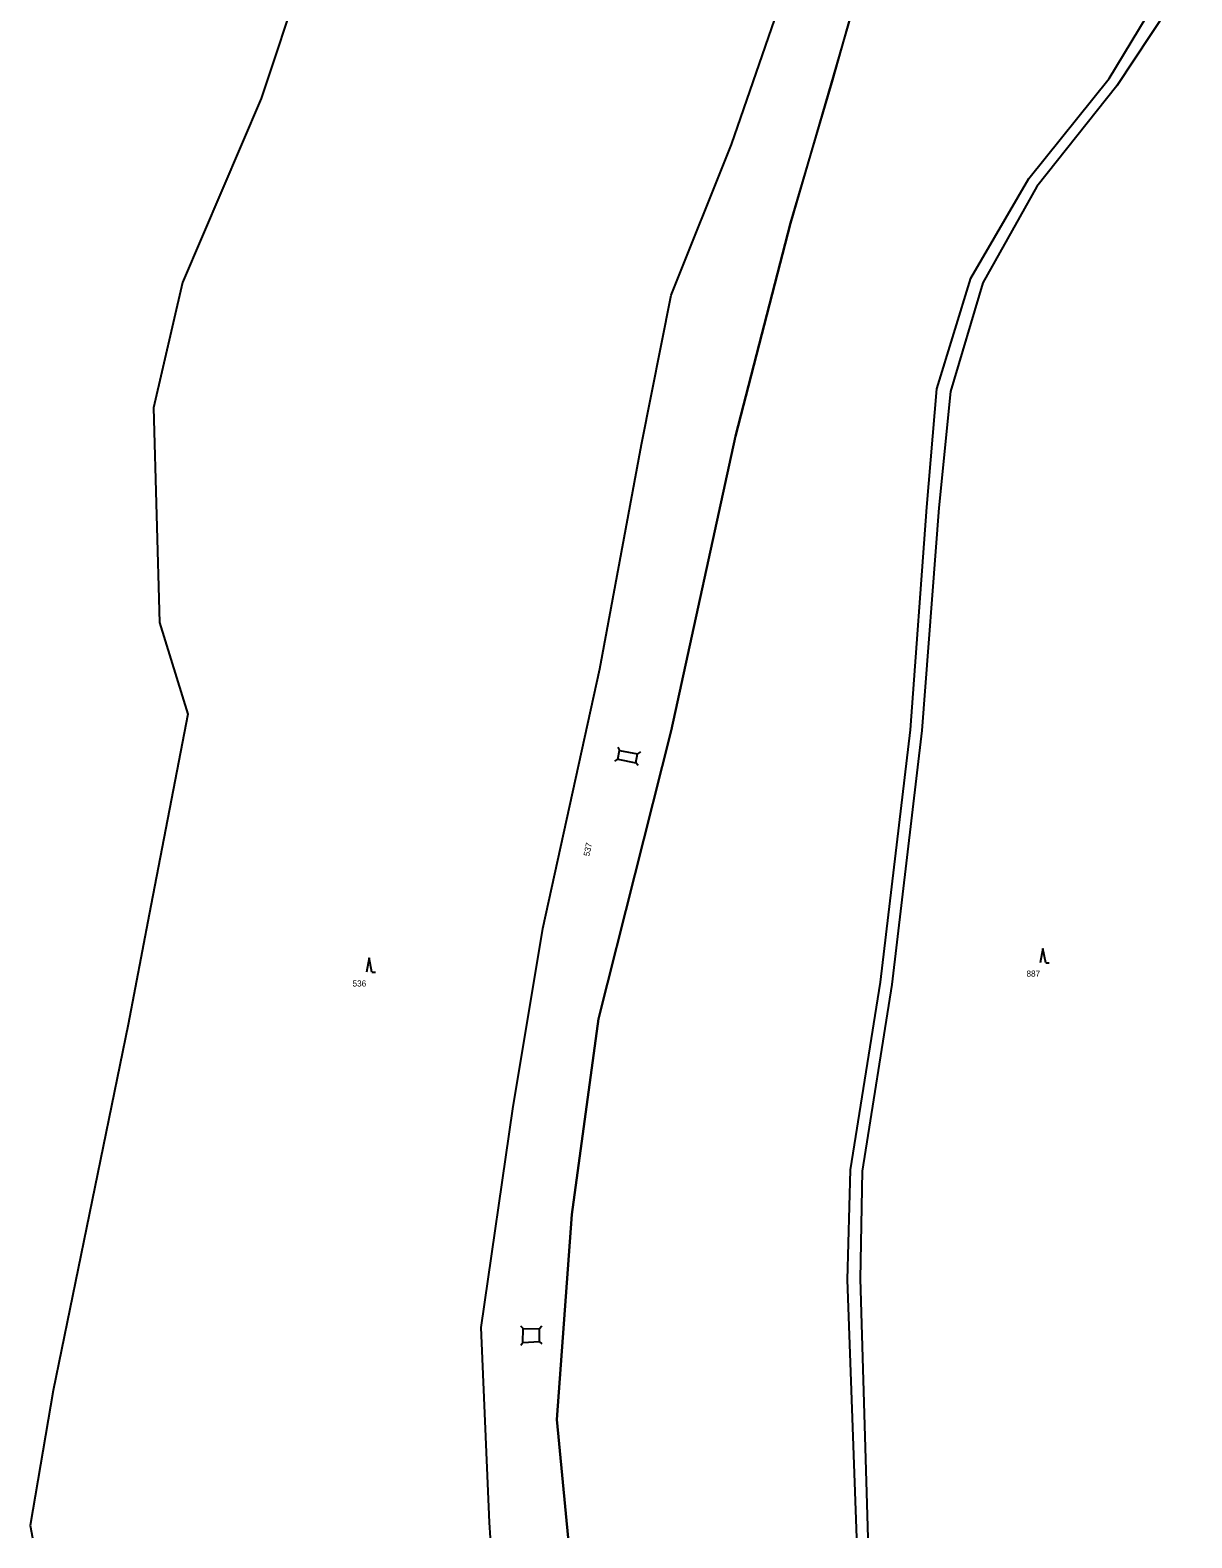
# Model space of a CAD drawing. Extents: x -520431 to -517205, y -1075927 to -1074013.
# Drawn here: x -520430.6 to -520107.9, y -1075925.4 to -1075506.4 of the extents above; entities that cross this region are included whole.
import ezdxf

# ---------------------------------------------------------------- set-up
doc = ezdxf.new("R2010")
doc.units = 0
for name, color, linetype in [('Hranice parcel', 7, 'Continuous'), ('Parcelní čísla', 7, 'Continuous'), ('Vnitřní kresba', 7, 'Continuous'), ('Vrstva 54', 7, 'Continuous'), ('Značky kultur', 7, 'Continuous')]:
    doc.layers.add(name, color=color, linetype=linetype)

msp = doc.modelspace()

# ---------------------------------------------------------------- linework, layer by layer
at = {"layer": 'Hranice parcel'}
for p, q in [((-520362.12, -1075512.33), (-520364.82, -1075520.45)), ((-520397.52, -1075752.17), (-520403.41, -1075782.76))]:
    msp.add_line(p, q, dxfattribs=at)
for points in [[(-520302.72, -1075925.35), (-520303, -1075921.12), (-520305.36, -1075866.94), (-520296.59, -1075806.18), (-520288.26, -1075756.04), (-520272.41, -1075683.94), (-520260.85, -1075621.57), (-520252.57, -1075580.03), (-520235.83, -1075538.19), (-520213.49, -1075473.53), (-520183.57, -1075419.35), (-520160.36, -1075375.59), (-520146.53, -1075345.11), (-520124.05, -1075300.26), (-520086.67, -1075251.23), (-520058.61, -1075213.11), (-520014.35, -1075160.9), (-520021.14, -1075139.22), (-520023.96, -1075136.16), (-519988.08, -1075098.67), (-519973.97, -1075115.61), (-519927.27, -1075074.86)], [(-520281.19, -1075925.35), (-520284.31, -1075892.43), (-520280.16, -1075835.55), (-520272.76, -1075781.1), (-520252.53, -1075701.11), (-520234.74, -1075619.24), (-520219.38, -1075560.04), (-520207.83, -1075520.9), (-520201.8, -1075499.48), (-520170.45, -1075435.1), (-520132.08, -1075363.03), (-520116.6, -1075331.33), (-520103.47, -1075305.84), (-520077.46, -1075262.04), (-520054.92, -1075231.63), (-520028.48, -1075200.53), (-519995.34, -1075165.5), (-519977.93, -1075145.65), (-519949.01, -1075120.12), (-519924.37, -1075102.58), (-519892.38, -1075083.85)], [(-520320.98, -1075333.84), (-520323.48, -1075348.86), (-520328.45, -1075402.76), (-520357.06, -1075497.07), (-520362.12, -1075512.33)], [(-520364.82, -1075520.45), (-520366.46, -1075525.4), (-520388.32, -1075576.55), (-520396.37, -1075611.37), (-520394.69, -1075671.04), (-520386.8, -1075696.53), (-520397.52, -1075752.17)], [(-520403.41, -1075782.76), (-520424.24, -1075884.37), (-520430.62, -1075921.97), (-520429.98, -1075925.35)]]:
    msp.add_lwpolyline(points, dxfattribs=at)
at = {"layer": 'Vnitřní kresba'}
for p, q in [((-520130.92, -1075519.83), (-520118.4, -1075499.23)), ((-520114.61, -1075500.54), (-520128.82, -1075521.92)), ((-520153.19, -1075547.67), (-520130.92, -1075519.83)), ((-520128.82, -1075521.92), (-520150.97, -1075549.91)), ((-520169.33, -1075575.31), (-520153.19, -1075547.67)), ((-520150.97, -1075549.91), (-520166.04, -1075576.65)), ((-520178.81, -1075606.09), (-520169.33, -1075575.31)), ((-520166.04, -1075576.65), (-520175.01, -1075606.86)), ((-520181.55, -1075639.01), (-520178.81, -1075606.09)), ((-520175.01, -1075606.86), (-520178.19, -1075639.13)), ((-520186.13, -1075700.83), (-520181.55, -1075639.01)), ((-520178.19, -1075639.13), (-520182.96, -1075701.06)), ((-520194.39, -1075770.98), (-520186.13, -1075700.83)), ((-520182.96, -1075701.06), (-520191.28, -1075771.6)), ((-520267.34, -1075705.7), (-520266.89, -1075706.59)), ((-520268.26, -1075709.54), (-520267.4, -1075709.03)), ((-520267.4, -1075709.03), (-520266.89, -1075706.59)), ((-520267.4, -1075709.03), (-520262.41, -1075710)), ((-520266.89, -1075706.59), (-520261.95, -1075707.55)), ((-520262.41, -1075710), (-520261.95, -1075707.55)), ((-520261.73, -1075710.73), (-520262.41, -1075710)), ((-520261.12, -1075706.99), (-520261.95, -1075707.55)), ((-520202.74, -1075823.08), (-520194.39, -1075770.98)), ((-520191.28, -1075771.6), (-520199.51, -1075823.51)), ((-520203.61, -1075853.66), (-520202.74, -1075823.08)), ((-520199.51, -1075823.51), (-520200.06, -1075853.35)), ((-520201, -1075925.35), (-520203.61, -1075853.66)), ((-520200.06, -1075853.35), (-520197.91, -1075925.35)), ((-520294.38, -1075866.41), (-520293.71, -1075867.15)), ((-520293.73, -1075871.06), (-520293.71, -1075867.15)), ((-520293.71, -1075867.15), (-520289.17, -1075867.29)), ((-520288.5, -1075866.55), (-520289.17, -1075867.29)), ((-520289.14, -1075870.83), (-520289.17, -1075867.29)), ((-520294.35, -1075871.85), (-520293.73, -1075871.06)), ((-520293.73, -1075871.06), (-520289.14, -1075870.83)), ((-520288.37, -1075871.47), (-520289.14, -1075870.83))]:
    msp.add_line(p, q, dxfattribs=at)
at = {"layer": 'Vrstva 54'}
for points in [[(-520303, -1075921.12), (-520305.36, -1075866.94), (-520296.59, -1075806.18), (-520288.26, -1075756.04), (-520272.41, -1075683.94), (-520260.85, -1075621.57), (-520252.57, -1075580.03), (-520235.83, -1075538.19), (-520213.49, -1075473.53), (-520183.57, -1075419.35), (-520160.36, -1075375.59), (-520146.53, -1075345.11), (-520124.05, -1075300.26), (-520086.67, -1075251.23), (-520058.61, -1075213.11), (-520014.35, -1075160.9), (-520021.14, -1075139.22), (-520023.96, -1075136.16), (-519988.08, -1075098.67), (-519973.97, -1075115.61), (-519927.27, -1075074.86)], [(-519892.38, -1075083.85), (-519924.37, -1075102.58), (-519949.01, -1075120.12), (-519977.93, -1075145.65), (-519995.34, -1075165.5), (-520028.48, -1075200.53), (-520054.92, -1075231.63), (-520077.46, -1075262.04), (-520103.47, -1075305.84), (-520116.6, -1075331.33), (-520132.08, -1075363.03), (-520170.45, -1075435.1), (-520201.8, -1075499.48), (-520219.38, -1075560.04), (-520234.74, -1075619.24), (-520252.53, -1075701.11), (-520272.76, -1075781.1), (-520280.16, -1075835.55), (-520284.31, -1075892.43), (-520281.19, -1075925.35)]]:
    msp.add_lwpolyline(points, dxfattribs=at)
at = {"layer": 'Značky kultur'}
for p, q in [((-520336.42, -1075764.21), (-520337.17, -1075768.21)), ((-520335.67, -1075768.21), (-520336.42, -1075764.21)), ((-520149.29, -1075761.63), (-520150.04, -1075765.63)), ((-520148.54, -1075765.63), (-520149.29, -1075761.63)), ((-520335.67, -1075768.21), (-520334.67, -1075768.21)), ((-520148.54, -1075765.63), (-520147.54, -1075765.63))]:
    msp.add_line(p, q, dxfattribs=at)

# ---------------------------------------------------------------- texts
at = {"layer": 'Parcelní čísla'}
msp.add_text('537', height=1.7, rotation=78, dxfattribs=at).set_placement((-520275.3, -1075736.11))
for s, p in [('887', (-520153.87, -1075769.43)), ('536', (-520341.07, -1075772.16))]:
    msp.add_text(s, height=1.7, dxfattribs=at).set_placement(p)

doc.saveas('drawing.dxf')
